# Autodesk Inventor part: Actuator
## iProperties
Created: 2008-05
Part Number: Actuator
Document SubType Name: Modeling
Density: 1 g/cm^3
Mass: 5.68097 g
Surface Area: 44.2655 cm^2
Volume: 5.68097 cm^3
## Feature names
1. Extrusion1
2. Extrusion3
3. Extrusion4
